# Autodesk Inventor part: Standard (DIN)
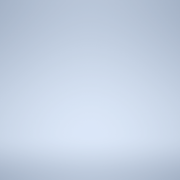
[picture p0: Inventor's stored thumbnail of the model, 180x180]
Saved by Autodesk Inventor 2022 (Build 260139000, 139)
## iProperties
Shininess: 64.0
Length Units: 11269
Angle Units: 11279
Time Units: 11290
Mass Units: 11283
Length Display Precision: 3
Angle Display Precision: 2
Compacted: True
Part Number: Standard (DIN)
Document SubType Name: Modeling
Created: 2002-07
Density: 1 g/cm^3
Material: Generico
Appearance: Default
Density: 0.0
Volumn: 0.0
Area: 0.0
PropertySet Name: Model Information
Control State: 0
Master: False
Checked Out: False
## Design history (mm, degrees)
